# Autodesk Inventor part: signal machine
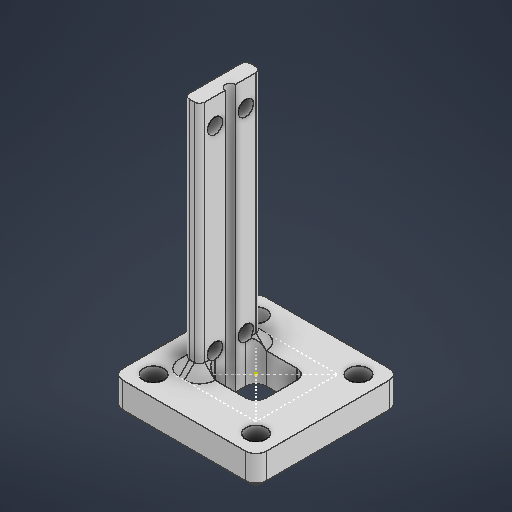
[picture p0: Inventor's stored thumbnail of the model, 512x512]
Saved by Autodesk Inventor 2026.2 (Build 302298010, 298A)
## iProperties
Created: 2026-05
Part Number: signal machine
Material: 일반
Document SubType Name: Modeling
Designer: work
Density: 1 g/cm^3
Appearance: 기본값
Author: work
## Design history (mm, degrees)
sketch "스케치1"
  geometry: L1 (-10, 10)-(10, 10); L2 (10, 10)-(10, -10); L3 (10, -10)-(-10, -10); L4 (-10, -10)-(-10, 10); L5 (-10, 10)-(10, -10); L6 (10, 10)-(-10, -10); L7 (-3, 5)-(3, 5); L8 (5, 3)-(5, -3); L9 (3, -5)-(-3, -5); L10 (-5, -3)-(-5, 3); L11 (-5, 5)-(5, -5); L12 (5, 5)-(-5, -5); L13 (-14, 14)-(14, 14); L14 (14, 14)-(14, -14); L15 (14, -14)-(-14, -14); L16 (-14, -14)-(-14, 14); L17 (-14, 14)-(14, -14); L18 (14, 14)-(-14, -14); C1 r 2 at (10, 10); C2 r 2 at (10, -10); C3 r 2 at (-10, -10); C4 r 2 at (-10, 10); A1 r 2 centre (3, 3) between (5, 3) and (3, 5); A2 r 2 centre (-3, 3) between (-3, 5) and (-5, 3); A3 r 2 centre (-3, -3) between (-5, -3) and (-3, -5); A4 r 2 centre (3, -3) between (3, -5) and (5, -3); 1 further point
  constraints: 36 end point, 8 centre point, 8 point on circle, 8 point on line, 8 tangent, 6 midpoint, 6 parallel, 4 coincident, 3 equal radius, 3 horizontal, 3 perpendicular
  dimensions: "d0" = 20 distance of L2.end L3.end; "d1" = 20 distance of L1.end L2.end; "d2" = 10 distance of L11.end L12.end; "d3" = 10 distance of L12.start L11.end; "d4" = 4 diameter of C1; "d5" = 4 diameter of C2; "d6" = 4 diameter of C3; "d7" = 4 diameter of C4; "d8" = 4 distance between parallel lines of L14 L2; "d9" = 4 distance between parallel lines of L15 L3; "d10" = 2 radius of A1 (derived)
extrude "돌출1" new body sketch "스케치1" distance "d11" = 6; taper "d12" = 0 deg
sketch "스케치2"
  geometry: 1 further point
sketch "스케치3"
  geometry: L1 (3, 0)-(3, 9); L2 (0, 9)-(6, 9); L3 (-3, 12)-(9, 12); L4 (9, 12)-(9, 0); L5 (9, 0)-(-3, 0); L6 (-3, 0)-(-3, 12); C1 r 1.5 at (0, 9); C2 r 1.5 at (6, 9); 1 further point
  constraints: 12 end point, 3 midpoint, 2 centre point, 2 coincident, 2 horizontal, 2 parallel, 1 perpendicular, 1 vertical
  dimensions: "d13" = 9 distance of L1.start L1.end; "d14" = 3 diameter of C1; "d15" = 3 diameter of C2; "d16" = 6 distance of L2.start L2.end; "d17" = 3 distance from line of point (3, 12) L2; "d18" = 3 distance from line of L4 L2.end
extrude "돌출2" join sketch "스케치3" distance "d19" = 3; taper "d20" = 0 deg
sketch "스케치4"
  geometry: L1 (0, 3)-(0, 9) reference; C1 r 1 at (0, 6); 3 further points
  constraints: 1 centre point, 1 midpoint
  dimensions: "d21" = 2 diameter of C1
extrude "돌출3" cut sketch "스케치4" extent not by distance; stored distance "d22" = 0; taper "d23" = 0 deg
fillet "모깎기1" dims "d24" = 1
fillet "모깎기3" dims "d26" = 2
sketch "스케치5"
  geometry: L1 (8, -8)-(-8, -8); L2 (-8, -8)-(-8, 8); L3 (-8, 8)-(8, 8); L4 (8, 8)-(8, -8); L5 (8, -8)-(-8, 8); L6 (-8, -8)-(8, 8); L7 (-8, -5)-(-8, 5) reference; 2 further points
  constraints: 12 end point, 4 midpoint, 2 parallel, 2 perpendicular, 1 horizontal
sketch "스케치6"
  geometry: L1 (-3, -5)-(-3, 5) reference; L2 (-1, -6)-(-2, -6) reference; L3 (0, -1)-(0, -5) reference; L4 (0, 5)-(0, 1) reference; L5 (-1, 6)-(-2, 6) reference; A1 r 1 centre (-2, 5) between (-2, 6) and (-3, 5) reference; A2 r 1 centre (-2, -5) between (-3, -5) and (-2, -6) reference; A3 r 1 centre (-1, -5) between (-1, -6) and (0, -5) reference; A4 r 1 centre (0, 0) between (0, 1) and (0, -1) reference; A5 r 1 centre (-1, 5) between (0, 5) and (-1, 6) reference; 1 further point
extrude "돌출4" join sketch "스케치6" distance "d27" = 40; taper "d28" = 0 deg
sketch "스케치7"
  geometry: L1 (0, 47)-(6, 47); L2 (3, 47)-(3, 9); L3 (4, 0)-(4, 52) reference; L4 (-2, 6)-(-2, 52) reference; L5 (0, 6)-(-2, 6) reference; L6 (0, 0)-(0, 6) reference; L7 (0, 0)-(2, 0) reference; L8 (2, 0)-(2, 52) reference; L9 (-2, 52)-(2, 52) reference; L10 (8, 6)-(8, 52) reference; L11 (4, 52)-(8, 52) reference; L12 (4, 0)-(4, 52) reference; L13 (4, 0)-(6, 0) reference; L14 (6, 0)-(6, 6) reference; L15 (8, 6)-(6, 6) reference; L16 (6, 9)-(0, 9); C1 r 1.5 at (0, 47); C2 r 1.5 at (6, 47); C3 r 1.5 at (0, 9) reference; C4 r 1.5 at (6, 9) reference; 1 further point
  constraints: 6 end point, 2 centre point, 2 coincident, 2 horizontal, 2 midpoint, 2 parallel
  dimensions: "d29" = 3 diameter of C1; "d30" = 3 diameter of C2; "d31" = 38 distance of L2.end L2.start
extrude "돌출5" cut sketch "스케치7" extent not by distance; stored distance "d32" = 0; taper "d33" = 0 deg
chamfer "모따기1" distance "d34" = 1; stored, may be unused: second distance "d35" = 2, angle "d36" = 45 deg
chamfer "모따기2" distance "d37" = 2; stored, may be unused: second distance "d38" = 2, angle "d39" = 45 deg
feature "Ǽ耀Ǿ耀Ȁ耀Ȃ耀Ȅ耀Ȇ耀Ȉ耀Ȋ耀" dims "d0" = 20, "d1" = 20, "d2" = 10, "d3" = 10, "d4" = 4, "d5" = 4, "d6" = 4, "d7" = 4, "d8" = 4, "d9" = 4, "d10" = 2 (derived), "d11" = 6, "d12" = 0, "d13" = 9, "d14" = 3, "d15" = 3, "d16" = 6, "d17" = 3, "d18" = 3, "d19" = 3, "d20" = 0, "d21" = 2, "d22" = 0, "d23" = 0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
node "솔리드1"
node "투영된 루프1"
node "투영된 루프2"
node "투영된 루프3"
